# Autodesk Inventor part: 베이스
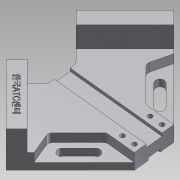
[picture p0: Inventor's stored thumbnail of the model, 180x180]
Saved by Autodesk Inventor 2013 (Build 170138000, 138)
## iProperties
Created: 2019-04
Part Number: 베이스
Material: 알루미늄 6061
Document SubType Name: Modeling
Designer: Administrator
Density: 2.71 g/cm^3
Mass: 602.17 g
Surface Area: 427.402 cm^2
Volume: 222.203 cm^3
Author: Administrator
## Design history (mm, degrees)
sketch "스케치1"
  geometry: L1 (-60, -60)-(31.716, -60); L2 (60, -60)-(60, -31.716); L3 (60, 60)-(-10, 60); L4 (-60, 60)-(-60, 10); L5 (-60, -60)-(60, 60); L6 (60, -60)-(-60, 60); L7 (-60, 10)-(-29.806, 10); L8 (-10, 10)-(-10, 29.806); L9 (-29.806, 10)-(-9.829, 29.977); L10 (31.716, -60)-(60, -31.716); L11 (-60, 10)-(-60, -60); L12 (-10, 60)-(-60, 60); L13 (-29.806, 10)-(-10, 10); L14 (-10, 29.806)-(-10, 60); L15 (31.716, -60)-(60, -60); L16 (60, -31.716)-(60, 60); 1 further point
  constraints: 32 end point, 9 parallel, 5 perpendicular, 4 horizontal, 2 midpoint, 2 point on line, 2 vertical
  dimensions: "d0" = 120 distance of L4.start L3.start; "d1" = 120 distance of L3.start L2.start; "d2" = 50 distance of L8.start L3.end; "d3" = 93 distance between parallel lines of L9 L10; "d4" = 20 distance from line of L10 L2.start
extrude "돌출1" new body sketch "스케치1" distance "d5" = 42; taper "d6" = 0 deg
sketch "스케치2"
  geometry: L1 (-60, -60)-(31.716, -60) reference; L2 (31.716, -60)-(60, -31.716) reference; L3 (-10, 29.806)-(-29.806, 10) reference; L4 (-60, 10)-(-60, -60) reference; L5 (-40, -60)-(-30, -40); L6 (-30, -40)-(11.716, -40); L7 (-20, -54.5)-(4, -54.5); L8 (-20, -45.5)-(4, -45.5); L9 (45.858, -45.858)-(0, 0); L10 (11.716, -40)-(31.716, -60); A1 r 4.5 centre (-20, -50) between (-20, -45.5) and (-20, -54.5); A2 r 4.5 centre (4, -50) between (4, -54.5) and (4, -45.5); 2 further points
  constraints: 12 end point, 4 point on circle, 4 tangent, 2 centre point, 2 point on line, 1 equal radius, 1 horizontal, 1 horizontal alignment, 1 midpoint, 1 parallel, 1 perpendicular
  dimensions: "d8" = 20 distance from line of L5.start L4; "d9" = 30 distance from line of L5.end L4; "d10" = 9 diameter of A1; "d11" = 40 distance from line of A1.centre L4; "d12" = 24 distance of A2.centre A1.centre; "d13" = 10 distance from line of L1 A1.centre; "d14" = 20 distance between parallel lines of L1 L6; "d15" = 20 distance between parallel lines of L10 L9; "d16" = 6 distance from line of point (31.716, -51.515) L2; "d17" = 12 distance of point (23.23, -43.029) point (31.716, -51.515); "d18" = 14 distance from line of point (31.716, -51.515) L9; "d19" = 14 distance from line of L9 point (23.23, -43.029)
extrude "돌출2" cut sketch "스케치2" distance "d20" = 34; taper "d21" = 0 deg
extrude "돌출3" cut sketch "스케치2" stored distance "d22" = 34; taper "d23" = 0 deg
sketch "스케치3"
  geometry: L1 (11.716, -40)-(31.716, -60) reference; L2 (31.716, -60)-(60, -31.716) reference; L3 (-10, 29.806)-(-29.806, 10) reference; L4 (-29.806, 10)-(-60, 10) reference; L5 (-60, 10)-(-60, -60) reference; L6 (-60, -60)-(-40, -60) reference; L7 (-40, -60)-(-30, -40) reference; L8 (-30, -40)-(11.716, -40) reference; L9 (-45, -60)-(-45, 10); L10 (-19.903, 19.903)-(45.858, -45.858); 1 further point
  constraints: 4 end point, 2 midpoint, 2 point on line, 1 vertical
  dimensions: "d24" = 15 distance between parallel lines of L9 L5
extrude "돌출4" cut sketch "스케치3" distance "d25" = 24; taper "d26" = 0 deg
sketch "스케치4"
  geometry: L1 (10, 29.806)-(29.806, 10) reference; L2 (-31.716, -60)-(-60, -31.716) reference; L3 (-45.858, -45.858)-(19.903, 19.903); L4 (-31.716, -51.515)-(-23.23, -43.029); 2 further points
  constraints: 4 end point, 4 midpoint, 1 parallel
  dimensions: "d27" = 6 distance from line of L4.start L2; "d28" = 12 distance of L4.start L4.end; "d29" = 14 distance between parallel lines of L4 L3
hole "구멍1" sketch "스케치4" diameter "d31" = 4.5; stored, may be unused: countersink angle "d35" = 90 deg, drill point angle "d37" = 118 deg; dims "d32" = 6, "d33" = 8, "d34" = 10, "d36" = 8
sketch "스케치5"
  geometry: L1 (10, 29.806)-(29.806, 10) reference; L2 (-31.716, -60)-(-60, -31.716) reference; L3 (-41.615, -50.101)-(24.146, 15.66); L4 (-50.101, -41.615)-(15.66, 24.146); 1 further point
  constraints: 4 end point, 4 point on line, 1 parallel, 1 perpendicular
  dimensions: "d38" = 12 distance between parallel lines of L4 L3; "d39" = 6 distance from line of L4 point (0, 0)
extrude "돌출5" cut sketch "스케치5" distance "d40" = 3; taper "d41" = 0 deg
sketch "스케치6"
  geometry: L1 (31.716, -60)-(11.716, -40) reference; L2 (60, -31.716)-(31.716, -60) reference; L3 (40, -11.716)-(60, -31.716) reference; L4 (40, 30)-(40, -11.716) reference; L5 (60, 40)-(40, 30) reference; L6 (60, 45)-(60, 40) reference; L7 (60, 45)-(-10, 45) reference; L8 (-10, 29.806)-(-10, 45) reference; L9 (-29.806, 10)-(-10, 29.806) reference; L10 (-45, 10)-(-29.806, 10) reference; L11 (-45, -60)-(-45, 10) reference; L12 (-40, -60)-(-45, -60) reference; L13 (-30, -40)-(-40, -60) reference; L14 (11.716, -40)-(-30, -40) reference; C1 r 2.25 at (31.716, -51.515) reference; C2 r 2.25 at (23.23, -43.029) reference; 1 further point
node "작업 평면1"
sketch "스케치7"
  geometry: L1 (60, -31.716)-(31.716, -60) reference; L2 (-29.806, 10)-(-10, 29.806) reference; L3 (-25.56, 14.246)-(40.201, -51.515); L4 (-14.246, 25.56)-(51.515, -40.201); 1 further point
  constraints: 4 end point, 4 point on line, 2 perpendicular
  dimensions: "d42" = 16 distance between parallel lines of L4 L3; "d43" = 8 distance from line of point (0, 0) L4
extrude "돌출6" cut sketch "스케치7" distance "d44" = 3.5; taper "d45" = 0 deg
fillet "모깎기1" dims "d46" = 5
sketch "스케치8"
  geometry: L1 (-45, 10)-(-60, 10) reference; L2 (-60, 10)-(-60, -60) reference; 2 further points
  constraints: 1 other
  dimensions: "d47" = 35 distance from line of L1 point (-52.5, -25); "d48" = 7.5 distance from line of L2 point (-52.5, -25)
feature "엠보싱1" sketch "스케치8" dims "d0" = 120, "d1" = 120, "d2" = 50, "d3" = 93, "d4" = 20, "d49" = 0.5, "d50" = 0
node "솔리드1"
mirror "대칭1"
mirror "대칭2"
